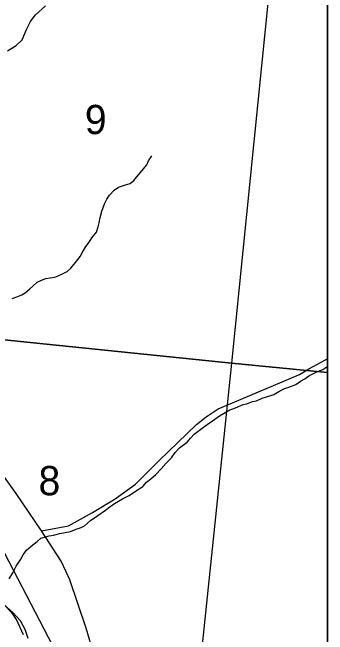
# Model space of a CAD drawing. Extents: x -7.5 to 26.5, y 3.5 to 25.5.
# Drawn here: x 0.992 to 1.443, y 20.216 to 21.108 of the extents above; entities that cross this region are included whole.
import ezdxf

# ---------------------------------------------------------------- set-up
doc = ezdxf.new("R2010")
doc.units = 0
for name, color, linetype in [('GM_X_Corporation', 7, 'Continuous'), ('GM_X_County_Road', 7, 'Continuous'), ('GM_X_Major_River', 7, 'Continuous'), ('GM_X_Minor_River', 7, 'Continuous'), ('GM_X_Rail_Line', 7, 'Continuous'), ('GM_X_Section_Text', 7, 'Continuous'), ('SH_Data', 7, 'Continuous')]:
    doc.layers.add(name, color=color, linetype=linetype)

msp = doc.modelspace()

# ---------------------------------------------------------------- linework, layer by layer
at = {"layer": 'GM_X_Corporation'}
for points in [[(1.44307, 17.6), (1.44307, 24.4), (-5.11944, 24.4)], [(1.44307, 18.5934), (1.44307, 22.07586)], [(1.39657, 21.5097), (1.30558, 20.60477), (0.31096, 20.70735)], [(0.31096, 20.70735), (1.30558, 20.60477), (1.21951, 19.77492)], [(1.00783, 20.21574), (0.99813, 20.23757), (0.99339, 20.24488), (0.97456, 20.26541)]]:
    msp.add_lwpolyline(points, dxfattribs=at)
for points in [[(1.44307, 20.59177), (1.44307, 21.50925), (1.39657, 21.5097), (1.30558, 20.60477)], [(1.44307, 19.61089), (1.44307, 20.59177), (1.30558, 20.60477), (1.21951, 19.77492), (1.21606, 19.71099), (1.22533, 19.68689), (1.23397, 19.66812), (1.24864, 19.64844), (1.26721, 19.63284)]]:
    msp.add_lwpolyline(points, close=True, dxfattribs=at)
at = {"layer": 'GM_X_County_Road'}
for points in [[(0.98515, 21.05265), (0.99753, 21.06039), (1.00583, 21.06827), (1.0123, 21.08304), (1.01807, 21.09458), (1.02461, 21.10372), (1.03959, 21.11695)], [(1.03365, 20.36485), (1.07256, 20.37181), (1.10686, 20.39104), (1.1389, 20.41071), (1.16832, 20.4316), (1.20227, 20.46565), (1.2553, 20.51706), (1.26926, 20.5281), (1.28665, 20.53942), (1.307, 20.548), (1.40301, 20.58879), (1.41651, 20.5968), (1.44002, 20.60986), (1.44307, 20.6115)], [(1.03365, 20.36485), (0.99735, 20.41835), (0.95565, 20.47627)], [(1.12799, 20.09711), (1.11341, 20.17129), (1.10855, 20.18814), (1.09741, 20.22528), (1.07425, 20.29465), (1.06887, 20.30618), (1.06169, 20.32119), (1.03365, 20.36485)]]:
    msp.add_lwpolyline(points, dxfattribs=at)
at = {"layer": 'GM_X_Major_River'}
msp.add_lwpolyline([(1.01447, 20.21032), (1.01032, 20.22337), (1.00349, 20.23574), (0.99248, 20.24786), (0.98028, 20.2585)], dxfattribs=at)
at = {"layer": 'GM_X_Minor_River'}
for points in [[(0.99169, 20.69745), (0.9986, 20.69987), (1.00553, 20.70267), (1.01057, 20.70554), (1.01645, 20.71103), (1.02154, 20.71542), (1.02744, 20.72129), (1.03361, 20.72412), (1.03976, 20.72619), (1.04624, 20.72711), (1.05274, 20.7284), (1.05773, 20.73013), (1.06353, 20.73297), (1.07048, 20.73653), (1.07559, 20.7413), (1.08232, 20.74942), (1.08907, 20.75793), (1.09191, 20.76316), (1.09715, 20.77209), (1.10193, 20.77839), (1.10594, 20.78471), (1.1123, 20.79285), (1.11484, 20.80037), (1.11617, 20.80602), (1.11757, 20.81357), (1.12017, 20.82299), (1.12394, 20.83312), (1.12721, 20.83985), (1.13083, 20.8458), (1.13753, 20.85279), (1.14413, 20.85712), (1.15412, 20.86058), (1.16065, 20.86263), (1.16572, 20.86664), (1.16969, 20.87144), (1.17561, 20.87808), (1.1796, 20.88364), (1.18434, 20.88918), (1.18682, 20.8948), (1.19163, 20.90223)], [(0.98767, 20.29588), (0.99252, 20.30446), (0.99741, 20.31417), (1.00421, 20.32419), (1.00746, 20.33016), (1.01226, 20.33722), (1.0189, 20.34269), (1.02749, 20.34961), (1.03296, 20.35399), (1.04485, 20.35738), (1.05095, 20.3583), (1.05977, 20.36066), (1.07545, 20.36392), (1.08315, 20.36707), (1.09045, 20.36948), (1.09547, 20.37197), (1.10369, 20.37929), (1.1142, 20.38691), (1.1251, 20.39451), (1.13134, 20.39924), (1.13795, 20.40395), (1.14957, 20.41039), (1.15923, 20.41538), (1.16701, 20.42081), (1.17865, 20.42801), (1.1838, 20.43429), (1.19005, 20.4394), (1.19748, 20.4456), (1.20497, 20.4537), (1.21208, 20.46144), (1.21995, 20.46953), (1.22514, 20.47695), (1.23144, 20.48357), (1.24197, 20.49157), (1.24673, 20.49749), (1.25224, 20.503), (1.2616, 20.51028), (1.27095, 20.51718), (1.27834, 20.52224), (1.28846, 20.52949), (1.30241, 20.53776), (1.31126, 20.54087), (1.32244, 20.54581), (1.32741, 20.54678), (1.33588, 20.55028), (1.34123, 20.55124), (1.34932, 20.55476), (1.3543, 20.55611), (1.3662, 20.55988), (1.37356, 20.56419), (1.3817, 20.56885), (1.38745, 20.57055), (1.39746, 20.57439), (1.40445, 20.57909), (1.41065, 20.58268), (1.41648, 20.58666), (1.4277, 20.59273), (1.43616, 20.59586), (1.442, 20.59984), (1.44307, 20.6004)]]:
    msp.add_lwpolyline(points, dxfattribs=at)
at = {"layer": 'GM_X_Rail_Line'}
msp.add_lwpolyline([(1.44307, 19.11009), (1.43574, 19.13421), (1.34268, 19.52848), (1.32404, 19.58202), (1.31306, 19.62574), (1.29522, 19.69677), (1.27132, 19.75532), (1.11302, 20.07849), (0.874, 20.53791), (0.83759, 20.61554), (0.82177, 20.66941), (0.82177, 20.73437), (0.82811, 20.80091), (0.85998, 20.88968), (0.94371, 21.07342), (0.97387, 21.14239), (1.00188, 21.19828), (1.04601, 21.25056), (1.10805, 21.30571), (1.18037, 21.39001), (1.22998, 21.44988), (1.32629, 21.56232), (1.41091, 21.65578), (1.44307, 21.68781)], dxfattribs=at)
at = {"layer": 'SH_Data'}
msp.add_line((1.44307, 24.4), (1.44307, 17.6), dxfattribs=at)

# ---------------------------------------------------------------- texts
at = {"layer": 'GM_X_Section_Text'}
for s, p in [('9', (1.09575, 20.93323)), ('8', (1.0295, 20.41573))]:
    msp.add_text(s, height=0.04186, rotation=0.00001, dxfattribs=at).set_placement(p)

doc.saveas('drawing.dxf')
